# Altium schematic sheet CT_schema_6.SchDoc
size 445 x 328 mm
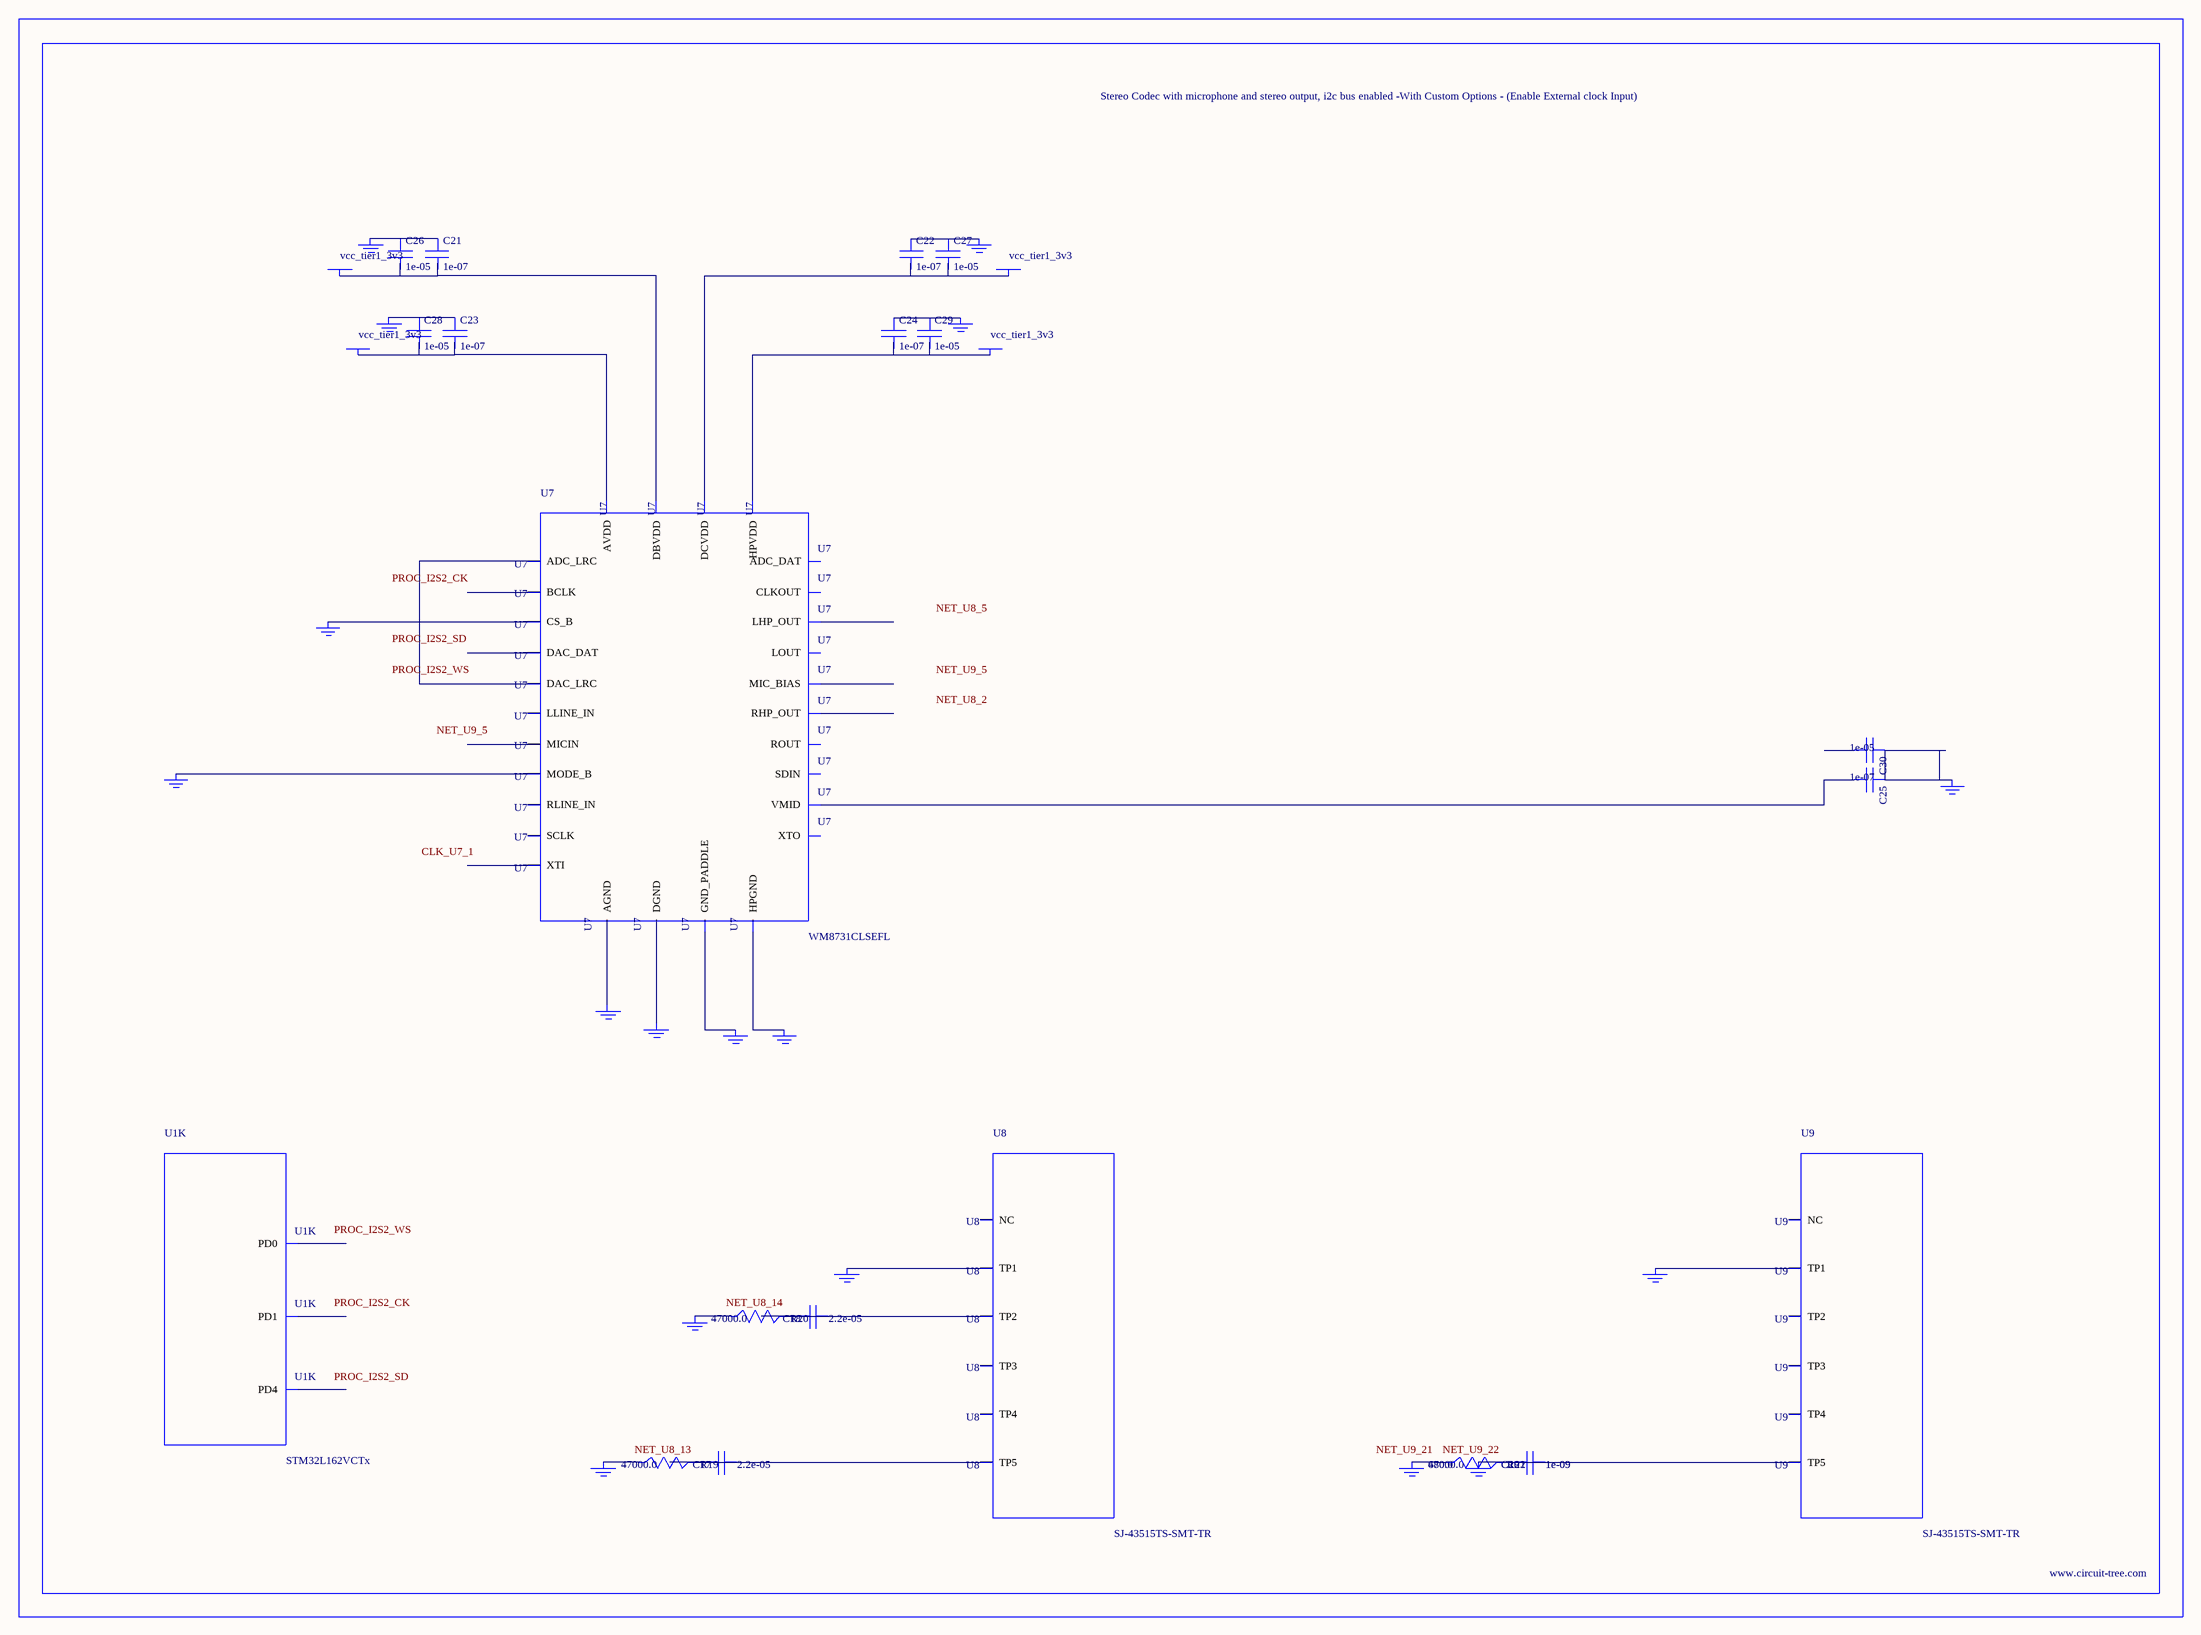
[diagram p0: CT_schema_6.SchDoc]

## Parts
BORDER5  (no value)
C17  2.2e-05  [C1210]
C18  2.2e-05  [C1210]
C19  1e-09  [C0402]
C20  1e-09  [C0402]
C21  1e-07  [C0402]
C22  1e-07  [C0402]
C23  1e-07  [C0402]
C24  1e-07  [C0402]
C25  1e-07  [C0402]
C26  1e-05  [C0805]
C27  1e-05  [C0805]
C28  1e-05  [C0805]
C29  1e-05  [C0805]
C30  1e-05  [C0805]
GND_INSTANCE_5_0  (no value)
GND_INSTANCE_5_1  (no value)
GND_INSTANCE_5_2  (no value)
GND_INSTANCE_5_3  (no value)
GND_INSTANCE_5_4  (no value)
GND_INSTANCE_5_5  (no value)
GND_INSTANCE_5_6  (no value)
GND_INSTANCE_5_7  (no value)
GND_INSTANCE_5_8  (no value)
GND_INSTANCE_5_9  (no value)
GND_INSTANCE_5_10  (no value)
GND_INSTANCE_5_11  (no value)
GND_INSTANCE_5_12  (no value)
GND_INSTANCE_5_13  (no value)
GND_INSTANCE_5_14  (no value)
GND_INSTANCE_5_15  (no value)
GND_INSTANCE_5_16  (no value)
POWER_INSTANCE_5_0  vcc_tier1_3v3
POWER_INSTANCE_5_1  vcc_tier1_3v3
POWER_INSTANCE_5_2  vcc_tier1_3v3
POWER_INSTANCE_5_3  vcc_tier1_3v3
R19  47000.0  [R0603]
R20  47000.0  [R0603]
R21  47000.0  [R0603]
R22  680.0  [R0603]
U1  STM32L162VCTx  [LQFP100]  (part K of 11)
U7  WM8731CLSEFL  [QFN-28]
U8  SJ-43515TS-SMT-TR  [SJ-43515TS-SMT-TR]
U9  SJ-43515TS-SMT-TR  [SJ-43515TS-SMT-TR]

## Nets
NetC17_1: C17.1 C17.2 R19.2 U8.5(TP5)
NetC18_1: C18.1 C18.2 R20.2 U8.2(TP2)
NetC19_1: C19.1 C19.2 C20.1 C20.2 GND_INSTANCE_5_16.0(GND) R21.2 R22.2 U9.5(TP5)
NetC21_1: C21.1 C26.1 GND_INSTANCE_5_1.0(GND)
NetC21_2: C21.2 C26.2 POWER_INSTANCE_5_1.0(PWR) U7.5(DBVDD)
NetC22_1: C22.1 C27.1 GND_INSTANCE_5_0.0(GND)
NetC22_2: C22.2 C27.2 POWER_INSTANCE_5_0.0(PWR) U7.3(DCVDD)
NetC23_1: C23.1 C28.1 GND_INSTANCE_5_4.0(GND)
NetC23_2: C23.2 C28.2 POWER_INSTANCE_5_3.0(PWR) U7.18(AVDD)
NetC24_1: C24.1 C29.1 GND_INSTANCE_5_2.0(GND)
NetC24_2: C24.2 C29.2 POWER_INSTANCE_5_2.0(PWR) U7.12(HPVDD)
NetC25_1: C25.1 C30.1 GND_INSTANCE_5_5.0(GND)
NetC25_2: C25.2 U7.20(VMID)
NetGND_INSTANCE_5_3_0: GND_INSTANCE_5_3.0(GND) U7.15(HPGND)
NetGND_INSTANCE_5_6_0: GND_INSTANCE_5_6.0(GND) U7.25(MODE_B)
NetGND_INSTANCE_5_7_0: GND_INSTANCE_5_7.0(GND) U7.26(CS_B)
NetGND_INSTANCE_5_8_0: GND_INSTANCE_5_8.0(GND) U7.29(GND_PADDLE)
NetGND_INSTANCE_5_9_0: GND_INSTANCE_5_9.0(GND) U7.4(DGND)
NetGND_INSTANCE_5_10_0: GND_INSTANCE_5_10.0(GND) U7.19(AGND)
NetGND_INSTANCE_5_11_0: GND_INSTANCE_5_11.0(GND) U8.1(TP1)
NetGND_INSTANCE_5_12_0: GND_INSTANCE_5_12.0(GND) R20.1
NetGND_INSTANCE_5_13_0: GND_INSTANCE_5_13.0(GND) R19.1
NetGND_INSTANCE_5_14_0: GND_INSTANCE_5_14.0(GND) U9.1(TP1)
NetGND_INSTANCE_5_15_0: GND_INSTANCE_5_15.0(GND) R21.1 R22.1
NetU7_9: U7.9(DAC_LRC) U7.11(ADC_LRC)

Not connected (* = marked no-connect by the designer): C30 2; U1 81(PD0) 82(PD1) 85(PD4); U7 1(XTI) 2(XTO) 6(CLKOUT) 7(BCLK) 8(DAC_DAT) 10(ADC_DAT) 13(LHP_OUT) 14(RHP_OUT) 16(LOUT) 17(ROUT) 21(MIC_BIAS) 22(MICIN) 23(RLINE_IN) 24(LLINE_IN) 27(SDIN) 28(SCLK); U8 3(TP3) 4(TP4) 6(NC); U9 2(TP2) 3(TP3) 4(TP4) 6(NC)

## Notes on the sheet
- Labels drawn without touching a wire or pin: CLK_U7_1, NET_U8_2, NET_U8_5, NET_U8_13, NET_U8_14, NET_U9_5, NET_U9_21, NET_U9_22, PROC_I2S2_CK, PROC_I2S2_SD, PROC_I2S2_WS

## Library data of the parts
BORDER5 = BORDER_PAGE5
C17 C18 = C1210C224K5RACTU
C19 C20 = C0402C102K3RAC
C21-C25 = C0402C104K3RACTU
C26-C30 = C0805C106K8RACTU
GND_INSTANCE_5_0-GND_INSTANCE_5_16 = GND
POWER_INSTANCE_5_0-POWER_INSTANCE_5_3 = PWR
R19-R21 = RC0603JR-0747KL
R22 = RC0603JR-07680RL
